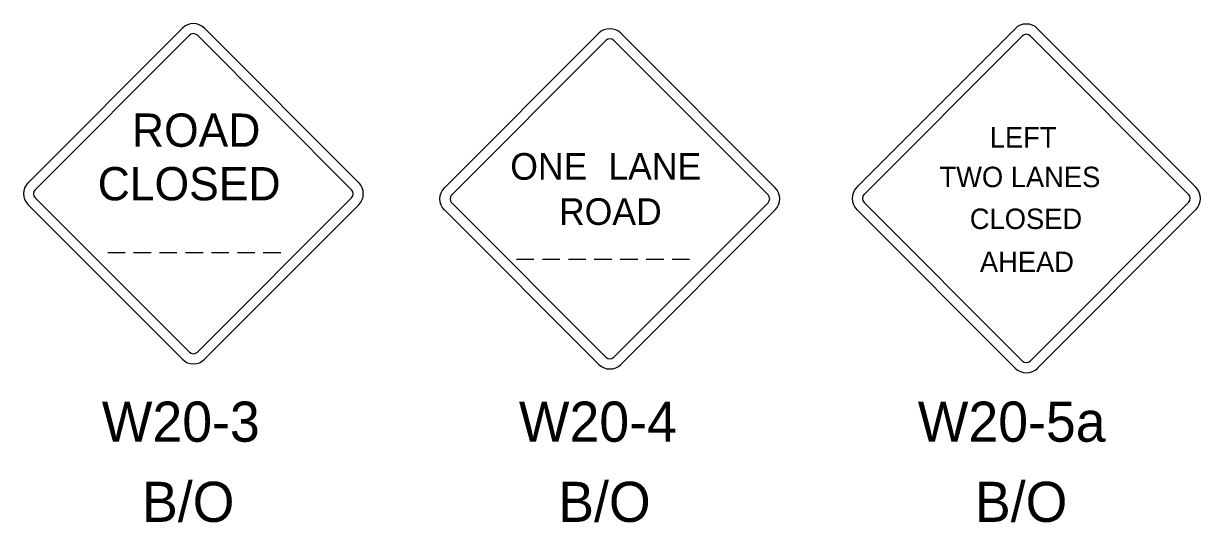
# Model space of a CAD drawing. Extents: x 10000 to 10794, y 10000 to 10499.
# Drawn here: x 10034.9 to 10137.6, y 10206.6 to 10250.1 of the extents above; entities that cross this region are included whole.
import ezdxf

# ---------------------------------------------------------------- set-up
doc = ezdxf.new("R2010")
doc.units = 0
for name, color, linetype in [('DSText', 7, 'Continuous'), ('DSTitle', 7, 'Continuous'), ('PlotBorder_dp', 7, 'Continuous')]:
    doc.layers.add(name, color=color, linetype=linetype)

msp = doc.modelspace()

# ---------------------------------------------------------------- linework, layer by layer
at = {"layer": 'DSText'}
for p, q in [((10035.25, 10236.2), (10048.73, 10249.67)), ((10050.64, 10249.67), (10064.12, 10236.2)), ((10071.6, 10235.75), (10085.08, 10249.22)), ((10086.99, 10249.22), (10100.47, 10235.75)), ((10107.59, 10235.81), (10121.4, 10249.62)), ((10123.37, 10249.62), (10137.18, 10235.81)), ((10048.73, 10220.81), (10035.25, 10234.28)), ((10064.12, 10234.28), (10050.64, 10220.81)), ((10085.08, 10220.36), (10071.6, 10233.83)), ((10100.47, 10233.83), (10086.99, 10220.36)), ((10121.4, 10220.03), (10107.59, 10233.85)), ((10137.18, 10233.85), (10123.37, 10220.03)), ((10042.2, 10230.11), (10043.72, 10230.11)), ((10044.46, 10230.11), (10045.99, 10230.11)), ((10046.72, 10230.11), (10048.25, 10230.11)), ((10048.99, 10230.11), (10050.52, 10230.11)), ((10051.25, 10230.11), (10052.78, 10230.11)), ((10053.52, 10230.11), (10055.04, 10230.11)), ((10055.78, 10230.11), (10057.31, 10230.11)), ((10077.88, 10229.54), (10079.4, 10229.54)), ((10080.14, 10229.54), (10081.67, 10229.54)), ((10082.41, 10229.54), (10083.93, 10229.54)), ((10084.67, 10229.54), (10086.2, 10229.54)), ((10086.93, 10229.54), (10088.46, 10229.54)), ((10089.2, 10229.54), (10090.73, 10229.54)), ((10091.46, 10229.54), (10092.99, 10229.54))]:
    msp.add_line(p, q, dxfattribs=at)
for centre, radius, start, end in [((10049.68, 10248.71), 1.36, 45, 135), ((10122.38, 10248.64), 1.39, 45, 135), ((10086.03, 10248.26), 1.36, 45, 135), ((10036.21, 10235.24), 1.36, 135, 225), ((10063.15, 10235.24), 1.36, 315, 45), ((10072.53, 10234.78), 1.36, 135, 225), ((10099.5, 10234.79), 1.36, 315, 45), ((10108.58, 10234.83), 1.39, 135, 225), ((10136.19, 10234.83), 1.39, 315, 45), ((10049.69, 10221.77), 1.36, 225, 315), ((10086.04, 10221.32), 1.36, 225, 315), ((10122.39, 10221.02), 1.39, 225, 315)]:
    msp.add_arc(centre, radius, start, end, dxfattribs=at)
at = {"layer": 'DSTitle'}
for p, q in [((10035.88, 10235.59), (10049.34, 10249.05)), ((10050.03, 10249.05), (10063.49, 10235.59)), ((10108.23, 10235.18), (10122.03, 10248.98)), ((10122.74, 10248.98), (10136.54, 10235.18)), ((10072.23, 10235.14), (10085.69, 10248.6)), ((10086.38, 10248.6), (10099.84, 10235.14)), ((10049.34, 10221.44), (10035.88, 10234.89)), ((10063.49, 10234.89), (10050.03, 10221.44)), ((10085.69, 10220.99), (10072.23, 10234.44)), ((10099.84, 10234.44), (10086.38, 10220.99)), ((10122.03, 10220.68), (10108.23, 10234.47)), ((10136.54, 10234.47), (10122.74, 10220.68))]:
    msp.add_line(p, q, dxfattribs=at)
for centre, radius, start, end in [((10049.68, 10248.7), 0.49, 45, 135), ((10122.38, 10248.63), 0.502, 45, 135), ((10086.03, 10248.25), 0.49, 45, 135), ((10036.22, 10235.24), 0.49, 135, 225), ((10063.14, 10235.24), 0.49, 315, 45), ((10072.57, 10234.79), 0.49, 135, 225), ((10099.49, 10234.79), 0.49, 315, 45), ((10108.59, 10234.83), 0.502, 135, 225), ((10136.18, 10234.83), 0.502, 315, 45), ((10049.68, 10221.78), 0.49, 225, 315), ((10086.03, 10221.33), 0.49, 225, 315), ((10122.38, 10221.03), 0.502, 225, 315)]:
    msp.add_arc(centre, radius, start, end, dxfattribs=at)

# ---------------------------------------------------------------- texts
at = {"layer": 'PlotBorder_dp'}
for s, height, p in [('ROAD', 2.901, (10044.32, 10239.33)), ('LEFT', 1.782, (10119.19, 10239.26)), ('ONE', 2.321, (10077.34, 10236.46)), ('LANE', 2.321, (10085.9, 10236.46)), ('CLOSED', 2.902, (10041.33, 10234.66)), ('TWO LANES', 1.783, (10114.8, 10235.81)), ('ROAD', 2.321, (10081.59, 10232.52)), ('CLOSED', 1.783, (10117.45, 10232.16)), ('AHEAD', 1.782, (10118.33, 10228.41)), ('W20-3', 3.5, (10041.69, 10213.62)), ('W20-4', 3.5, (10078.09, 10213.62)), ('W20-5a', 3.5, (10112.91, 10213.62)), ('B/O', 3.5, (10045.2, 10206.63)), ('B/O', 3.5, (10081.53, 10206.63)), ('B/O', 3.5, (10117.9, 10206.63))]:
    msp.add_text(s, height=height, dxfattribs=at).set_placement(p)

doc.saveas('drawing.dxf')
